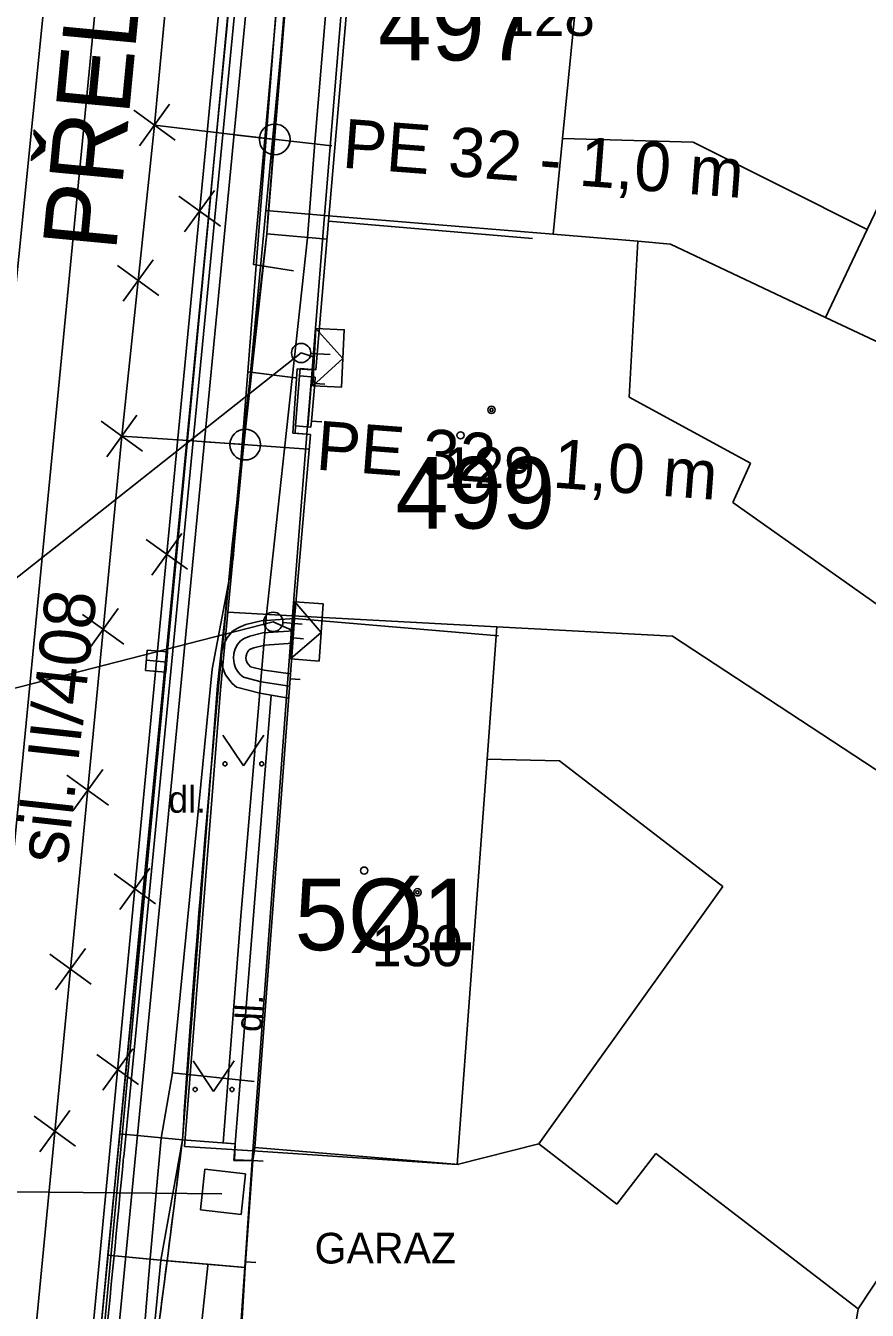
# Model space of a CAD drawing. Extents: x -643342 to -638635, y -1201752 to -1189948.
# Drawn here: x -639498.67 to -639478.12, y -1192813.04 to -1192781.64 of the extents above; entities that cross this region are included whole.
import ezdxf

# ---------------------------------------------------------------- set-up
doc = ezdxf.new("R2010")
doc.units = 0
for name, color, linetype in [('2', 7, 'Continuous'), ('IS_EL_NN_NADZEMNÍ', 7, 'Continuous'), ('IS_EL_NN_PODZEMNÍ', 7, 'Continuous'), ('IS_PLYN_STL', 7, 'Continuous'), ('IS_TELEF_MISTNI_ZAMERENO', 7, 'Continuous'), ('IS_VODOVOD_PRIPOJKA DOMOVNÍ', 7, 'Continuous'), ('IS_VODOVOD_PRIPOJKA HYDRANT', 7, 'Continuous'), ('K-HRANICE_KN', 7, 'Continuous'), ('K-SLUCKOVE CARY', 7, 'Continuous'), ('K-ČÍSLA_PARCEL', 7, 'Continuous'), ('kanalizace_dešťová_stávající', 7, 'Continuous'), ('N-CHODNIK', 7, 'Continuous'), ('N-KAN_DEST_TRASA-NÁVRH', 7, 'Continuous'), ('N-OBVOD STAVBY 06', 7, 'Continuous'), ('N-OSA', 7, 'Continuous'), ('N-rusene_vedeni', 7, 'Continuous'), ('N-SILNICE', 7, 'Continuous'), ('N-SRAFY_PLOCHY', 7, 'Continuous'), ('RWE_STL_PRIPOJKY', 7, 'Continuous'), ('RWE_STL_RADY', 7, 'Continuous'), ('tomaštík - Džuganovi - Vrstva 36', 7, 'Continuous'), ('Z-budovy', 7, 'Continuous'), ('Z-hrany_a_čáry', 7, 'Continuous'), ('Z-popisy', 7, 'Continuous'), ('Z-vchody_vjezdy', 7, 'Continuous'), ('Z-značky', 7, 'Continuous'), ('Z-šachty_poklopy', 7, 'Continuous')]:
    doc.layers.add(name, color=color, linetype=linetype)

msp = doc.modelspace()

# ---------------------------------------------------------------- linework, layer by layer
at = {"layer": '2'}
for centre in [(-639492.586, -1192784.42), (-639493.306, -1192791.88)]:
    msp.add_circle(centre, 0.375, dxfattribs=at)
at = {"layer": 'IS_EL_NN_NADZEMNÍ'}
for points in [[(-639491.653, -1192790.439), (-639490.92, -1192789.774), (-639491.585, -1192789.041)], [(-639491.705, -1192789.651), (-639491.235, -1192789.674)], [(-639492.202, -1192797.117), (-639491.453, -1192796.472), (-639492.098, -1192795.722)], [(-639492.386, -1192796.229), (-639491.917, -1192796.267)]]:
    msp.add_lwpolyline(points, dxfattribs=at)
for centre in [(-639491.94, -1192789.64), (-639492.62, -1192796.21)]:
    msp.add_circle(centre, 0.235, dxfattribs=at)
at = {"layer": 'IS_EL_NN_PODZEMNÍ'}
for p, q in [((-639503.93, -1192799.12), (-639491.94, -1192789.64)), ((-639491.94, -1192789.64), (-639491.62, -1192789.74)), ((-639503.93, -1192799.12), (-639492.62, -1192796.21)), ((-639492.62, -1192796.21), (-639492.15, -1192796.42))]:
    msp.add_line(p, q, dxfattribs=at)
for points in [[(-639491.653, -1192790.439), (-639491.585, -1192789.041), (-639490.886, -1192789.074), (-639490.954, -1192790.473)], [(-639492.202, -1192797.117), (-639492.098, -1192795.722), (-639491.401, -1192795.773), (-639491.504, -1192797.169)]]:
    msp.add_lwpolyline(points, close=True, dxfattribs=at)
at = {"layer": 'IS_PLYN_STL'}
for p, q in [((-639495.52, -1192784.07), (-639493.97, -1192767.19)), ((-639496.32, -1192791.67), (-639495.52, -1192784.07)), ((-639498.43, -1192813.58), (-639496.32, -1192791.67))]:
    msp.add_line(p, q, dxfattribs=at)
for points in [[(-639495.52, -1192784.07), (-639493.54, -1192784.31), (-639491.19, -1192784.58)], [(-639496.32, -1192791.67), (-639494.83, -1192791.77), (-639491.77, -1192791.99)]]:
    msp.add_lwpolyline(points, dxfattribs=at)
at = {"layer": 'IS_TELEF_MISTNI_ZAMERENO'}
for p, q in [((-639492.3, -1192778.08), (-639493.24, -1192790.1)), ((-639493.24, -1192790.1), (-639492.3, -1192778.08)), ((-639493.24, -1192790.1), (-639493.6, -1192794.66)), ((-639493.6, -1192794.66), (-639493.24, -1192790.1)), ((-639493.24, -1192790.1), (-639492.08, -1192790.25)), ((-639493.6, -1192794.66), (-639494.11, -1192797.37)), ((-639494.11, -1192797.37), (-639493.6, -1192794.66)), ((-639494.11, -1192797.37), (-639495.08, -1192807.23)), ((-639495.08, -1192807.23), (-639494.11, -1192797.37)), ((-639495.08, -1192807.23), (-639495.36, -1192808.83)), ((-639495.36, -1192808.83), (-639495.08, -1192807.23)), ((-639495.08, -1192807.23), (-639493.09, -1192807.44)), ((-639495.36, -1192808.83), (-639495.63, -1192811.77)), ((-639495.63, -1192811.77), (-639495.36, -1192808.83)), ((-639495.63, -1192811.77), (-639496.16, -1192818.41)), ((-639496.16, -1192818.41), (-639495.63, -1192811.77))]:
    msp.add_line(p, q, dxfattribs=at)
at = {"layer": 'IS_VODOVOD_PRIPOJKA DOMOVNÍ'}
msp.add_lwpolyline([(-639499.852, -1192774.557), (-639499.731, -1192774.571), (-639492.02, -1192775.45), (-639493.1, -1192787.48), (-639492.131, -1192787.636)], dxfattribs=at)
at = {"layer": 'IS_VODOVOD_PRIPOJKA HYDRANT'}
msp.add_lwpolyline([(-639503.418, -1192810.065), (-639503.2, -1192810.095), (-639493.88, -1192810.19)], dxfattribs=at)
at = {"layer": 'K-HRANICE_KN'}
for p, q in [((-639491.69, -1192774.35), (-639492.8, -1192786.16)), ((-639475.11, -1192780.31), (-639478.12, -1192786.62)), ((-639492.8, -1192786.16), (-639493.73, -1192795.97)), ((-639491.37, -1192786.28), (-639492.8, -1192786.16)), ((-639491.37, -1192786.28), (-639485.79, -1192786.74)), ((-639485.79, -1192786.74), (-639483.72, -1192786.91)), ((-639478.12, -1192786.62), (-639479.14, -1192788.77)), ((-639483.72, -1192786.91), (-639482.92, -1192786.98)), ((-639482.92, -1192786.98), (-639479.14, -1192788.77)), ((-639479.14, -1192788.77), (-639476.76, -1192789.89)), ((-639493.73, -1192795.97), (-639493.91, -1192797.87)), ((-639492.15, -1192796.06), (-639493.73, -1192795.97)), ((-639492.15, -1192796.06), (-639487.16, -1192796.33)), ((-639487.16, -1192796.33), (-639482.87, -1192796.56)), ((-639482.87, -1192796.56), (-639475.39, -1192801.48)), ((-639493.91, -1192797.87), (-639494.79, -1192809.03)), ((-639474.95, -1192807.86), (-639478.34, -1192813)), ((-639493.12, -1192809.14), (-639494.79, -1192809.03)), ((-639494.4, -1192827.84), (-639493.12, -1192809.14)), ((-639478.34, -1192813), (-639481.06, -1192829.36))]:
    msp.add_line(p, q, dxfattribs=at)
at = {"layer": 'K-SLUCKOVE CARY'}
for p, q in [((-639485.08, -1192779.59), (-639485.56, -1192784.4)), ((-639490.87, -1192780.14), (-639491.37, -1192786.28)), ((-639485.56, -1192784.4), (-639485.79, -1192786.74)), ((-639485.56, -1192784.4), (-639482.37, -1192784.49)), ((-639482.37, -1192784.49), (-639478.12, -1192786.62)), ((-639491.37, -1192786.28), (-639491.67, -1192790.05)), ((-639483.72, -1192786.91), (-639483.93, -1192790.72)), ((-639492.04, -1192790.03), (-639492.14, -1192791.6)), ((-639491.67, -1192790.05), (-639492.04, -1192790.03)), ((-639491.67, -1192790.05), (-639491.8, -1192791.62)), ((-639483.93, -1192790.72), (-639480.97, -1192792.33)), ((-639491.8, -1192791.62), (-639492.15, -1192796.06)), ((-639491.8, -1192791.62), (-639492.14, -1192791.6)), ((-639480.97, -1192792.33), (-639481.4, -1192793.29)), ((-639481.4, -1192793.29), (-639475.59, -1192797.41)), ((-639492.15, -1192796.06), (-639493.12, -1192809.14)), ((-639487.16, -1192796.33), (-639487.4, -1192799.57)), ((-639487.4, -1192799.57), (-639488.13, -1192809.47)), ((-639485.63, -1192799.61), (-639487.4, -1192799.57)), ((-639481.64, -1192802.68), (-639485.63, -1192799.61)), ((-639486.14, -1192808.97), (-639481.64, -1192802.68)), ((-639488.13, -1192809.47), (-639486.14, -1192808.97)), ((-639486.14, -1192808.97), (-639484.23, -1192810.44)), ((-639488.13, -1192809.47), (-639493.12, -1192809.14)), ((-639484.23, -1192810.44), (-639483.28, -1192809.2)), ((-639481.19, -1192810.81), (-639483.28, -1192809.2)), ((-639478.34, -1192813), (-639481.19, -1192810.81))]:
    msp.add_line(p, q, dxfattribs=at)
at = {"layer": 'K-ČÍSLA_PARCEL'}
for centre in [(-639488.048, -1192791.653), (-639490.402, -1192802.289)]:
    msp.add_circle(centre, 0.0875, dxfattribs=at)
at = {"layer": 'kanalizace_dešťová_stávající'}
msp.add_lwpolyline([(-639500.838, -1192858.606), (-639498.4, -1192827.95), (-639495.47, -1192797.17), (-639492.53, -1192766.39), (-639489.24, -1192732.18), (-639488.56, -1192730.68), (-639487.73, -1192718.33)], dxfattribs=at)
at = {"layer": 'N-CHODNIK'}
msp.add_lwpolyline([(-639495.215, -1192811.823), (-639493.308, -1192811.988), (-639493.3, -1192811.85), (-639493.12, -1192809.37), (-639493.569, -1192809.371), (-639493.551, -1192808.967), (-639494.84, -1192808.87)], close=True, dxfattribs=at)
at = {"layer": 'N-KAN_DEST_TRASA-NÁVRH'}
msp.add_lwpolyline([(-639498.884, -1192834.039), (-639503.116, -1192829.951), (-639498.124, -1192780.201), (-639493.988, -1192740.511), (-639490.998, -1192720.223)], dxfattribs=at)
at = {"layer": 'N-OBVOD STAVBY 06'}
for points in [[(-639490.763, -1192774.407), (-639491.607, -1192784.497), (-639491.784, -1192786.822), (-639492.345, -1192791.985), (-639492.793, -1192796.103), (-639493.413, -1192803.401), (-639493.844, -1192808.945)], [(-639494.218, -1192811.91), (-639493.308, -1192811.988), (-639493.12, -1192809.37), (-639493.581, -1192809.371), (-639493.551, -1192808.967), (-639493.844, -1192808.945)], [(-639494.218, -1192811.91), (-639494.222, -1192811.939), (-639494.961, -1192818.864)]]:
    msp.add_lwpolyline(points, dxfattribs=at)
at = {"layer": 'N-OSA'}
msp.add_lwpolyline([(-639495.549, -1192766.512), (-639499.658, -1192808.961)], dxfattribs=at)
at = {"layer": 'N-rusene_vedeni'}
for p, q in [((-639495.154, -1192783.563), (-639495.886, -1192784.577)), ((-639496.027, -1192783.704), (-639495.013, -1192784.436)), ((-639494.926, -1192785.808), (-639493.913, -1192786.539)), ((-639494.054, -1192785.667), (-639494.785, -1192786.68)), ((-639495.554, -1192787.363), (-639496.286, -1192788.377)), ((-639496.427, -1192787.504), (-639495.413, -1192788.236)), ((-639496.827, -1192791.304), (-639495.813, -1192792.036)), ((-639495.954, -1192791.163), (-639496.686, -1192792.177)), ((-639495.727, -1192794.194), (-639494.714, -1192794.926)), ((-639494.855, -1192794.054), (-639495.587, -1192795.067)), ((-639497.282, -1192796.027), (-639496.268, -1192796.758)), ((-639496.409, -1192795.886), (-639497.141, -1192796.899)), ((-639496.787, -1192799.815), (-639497.519, -1192800.828)), ((-639497.66, -1192799.955), (-639496.646, -1192800.687)), ((-639496.506, -1192802.367), (-639495.493, -1192803.099)), ((-639495.634, -1192802.226), (-639496.365, -1192803.239)), ((-639498.081, -1192804.332), (-639497.068, -1192805.064)), ((-639497.209, -1192804.191), (-639497.94, -1192805.205)), ((-639496.927, -1192806.783), (-639495.913, -1192807.515)), ((-639496.054, -1192806.642), (-639496.786, -1192807.656)), ((-639498.462, -1192808.29), (-639497.449, -1192809.021)), ((-639497.59, -1192808.149), (-639498.322, -1192809.162))]:
    msp.add_line(p, q, dxfattribs=at)
at = {"layer": 'N-SILNICE'}
for p, q in [((-639492.314, -1192766.825), (-639496.423, -1192809.274)), ((-639492.165, -1192766.839), (-639496.274, -1192809.288)), ((-639494.84, -1192808.87), (-639496.37, -1192808.722)), ((-639495.37, -1192811.81), (-639496.657, -1192811.685))]:
    msp.add_line(p, q, dxfattribs=at)
for centre, radius, start, end in [((-638654.028, -1192849.484), 841.096, 173.995633, 175.721181), ((-639079.22, -1192836.375), 416.529, 173.15477, 176.21376), ((-641212.11, -1192592.417), 1730.858, 352.569253, 352.816044), ((-654430.042, -1191365.485), 15003.249, 354.4395848, 354.4777819), ((-654430.042, -1191365.485), 15003.399, 354.4395848, 354.4777819)]:
    msp.add_arc(centre, radius, start, end, dxfattribs=at)
at = {"layer": 'N-SRAFY_PLOCHY'}
for p, q in [((-639493.753, -1192781.684), (-639492.4, -1192767.706)), ((-639494.927, -1192793.814), (-639493.753, -1192781.684)), ((-639495.981, -1192804.707), (-639494.927, -1192793.814)), ((-639496.939, -1192814.599), (-639495.981, -1192804.707)), ((-639496.37, -1192808.722), (-639496.657, -1192811.685)), ((-639494.84, -1192808.87), (-639496.37, -1192808.722)), ((-639495.215, -1192811.823), (-639494.84, -1192808.87)), ((-639496.657, -1192811.685), (-639497.331, -1192818.633)), ((-639495.215, -1192811.823), (-639496.657, -1192811.685)), ((-639496.657, -1192811.685), (-639495.215, -1192811.823)), ((-639495.77, -1192816.072), (-639495.215, -1192811.823))]:
    msp.add_line(p, q, dxfattribs=at)
for points in [[(-639493.747, -1192781.625), (-639494.005, -1192784.291), (-639494.312, -1192787.48), (-639494.548, -1192789.97), (-639494.823, -1192792.867), (-639495.07, -1192795.478), (-639495.359, -1192798.278), (-639495.518, -1192799.926), (-639495.721, -1192802.017), (-639495.878, -1192803.643), (-639496.151, -1192806.461), (-639496.37, -1192808.722), (-639494.84, -1192808.87), (-639494.591, -1192805.337), (-639494.289, -1192801.533), (-639493.965, -1192797.861), (-639493.757, -1192795.722), (-639493.595, -1192794.067), (-639493.293, -1192791.209), (-639492.885, -1192787.614), (-639492.78, -1192786.73), (-639492.363, -1192781.385)], [(-639495.215, -1192811.823), (-639493.308, -1192811.988), (-639493.3, -1192811.85), (-639493.12, -1192809.37), (-639493.569, -1192809.371), (-639493.551, -1192808.967), (-639494.84, -1192808.87), (-639495.215, -1192811.823)]]:
    msp.add_lwpolyline(points, dxfattribs=at)
at = {"layer": 'RWE_STL_PRIPOJKY'}
for p, q in [((-639493.58, -1192784.305), (-639492.586, -1192784.42)), ((-639494.304, -1192791.808), (-639493.306, -1192791.88))]:
    msp.add_line(p, q, dxfattribs=at)
at = {"layer": 'RWE_STL_RADY'}
msp.add_lwpolyline([(-639497.844, -1192828.492), (-639491.5, -1192762.757), (-639493.022, -1192762.61), (-639492.143, -1192753.805), (-639490.591, -1192738.259)], dxfattribs=at)
at = {"layer": 'Z-budovy'}
for p, q in [((-639490.733, -1192780.127), (-639491.27, -1192786.42)), ((-639491.27, -1192786.42), (-639491.58, -1192790.05)), ((-639491.27, -1192786.42), (-639486.288, -1192786.845)), ((-639486.288, -1192786.845), (-639491.27, -1192786.42)), ((-639491.964, -1192790.017), (-639491.98, -1192790.2)), ((-639491.98, -1192790.2), (-639491.596, -1192790.233)), ((-639491.58, -1192790.05), (-639491.964, -1192790.017)), ((-639491.609, -1192790.382), (-639491.687, -1192791.303)), ((-639491.596, -1192790.233), (-639491.609, -1192790.382)), ((-639492.08, -1192791.42), (-639492.09, -1192791.6)), ((-639491.7, -1192791.452), (-639492.08, -1192791.42)), ((-639491.687, -1192791.303), (-639491.7, -1192791.452)), ((-639491.716, -1192791.632), (-639492.1, -1192796.13)), ((-639492.09, -1192791.6), (-639491.716, -1192791.632)), ((-639492.1, -1192796.13), (-639492.136, -1192796.604)), ((-639487.118, -1192796.556), (-639492.1, -1192796.13)), ((-639492.1, -1192796.13), (-639487.118, -1192796.556)), ((-639492.136, -1192796.604), (-639492.211, -1192797.604)), ((-639492.211, -1192797.604), (-639493.07, -1192809.06)), ((-639493.07, -1192809.06), (-639493.12, -1192809.37)), ((-639493.07, -1192809.06), (-639488.087, -1192809.469)), ((-639488.087, -1192809.469), (-639493.07, -1192809.06)), ((-639493.12, -1192809.37), (-639493.3, -1192811.85)), ((-639493.3, -1192811.85), (-639493.39, -1192813.37))]:
    msp.add_line(p, q, dxfattribs=at)
at = {"layer": 'Z-hrany_a_čáry'}
for p, q in [((-639491.75, -1192774.21), (-639492.78, -1192786.73)), ((-639493.35, -1192777.33), (-639495.68, -1192801.91)), ((-639492.78, -1192786.73), (-639493.98, -1192797.77)), ((-639492.78, -1192786.73), (-639491.307, -1192786.856)), ((-639491.98, -1192790.2), (-639492.08, -1192791.42)), ((-639491.681, -1192790.226), (-639491.781, -1192791.445)), ((-639492.92, -1192796.182), (-639493.29, -1192796.277)), ((-639492.1, -1192796.13), (-639492.92, -1192796.182)), ((-639493.62, -1192796.44), (-639493.747, -1192796.601)), ((-639493.465, -1192796.351), (-639493.62, -1192796.44)), ((-639493.29, -1192796.277), (-639493.465, -1192796.351)), ((-639492.873, -1192796.48), (-639493.194, -1192796.562)), ((-639492.123, -1192796.432), (-639492.873, -1192796.48)), ((-639493.831, -1192796.757), (-639493.878, -1192796.929)), ((-639493.747, -1192796.601), (-639493.831, -1192796.757)), ((-639493.495, -1192796.766), (-639493.551, -1192796.869)), ((-639493.42, -1192796.671), (-639493.495, -1192796.766)), ((-639493.331, -1192796.62), (-639493.42, -1192796.671)), ((-639493.194, -1192796.562), (-639493.331, -1192796.62)), ((-639492.826, -1192796.777), (-639493.097, -1192796.847)), ((-639492.146, -1192796.734), (-639492.826, -1192796.777)), ((-639493.878, -1192796.929), (-639493.899, -1192797.108)), ((-639493.899, -1192797.108), (-639493.865, -1192797.315)), ((-639493.583, -1192796.986), (-639493.596, -1192797.101)), ((-639493.596, -1192797.101), (-639493.575, -1192797.232)), ((-639493.551, -1192796.869), (-639493.583, -1192796.986)), ((-639493.287, -1192797.044), (-639493.293, -1192797.094)), ((-639493.293, -1192797.094), (-639493.284, -1192797.15)), ((-639493.27, -1192796.981), (-639493.287, -1192797.044)), ((-639493.244, -1192796.932), (-639493.27, -1192796.981)), ((-639493.221, -1192796.903), (-639493.244, -1192796.932)), ((-639493.198, -1192796.889), (-639493.221, -1192796.903)), ((-639493.097, -1192796.847), (-639493.198, -1192796.889)), ((-639493.865, -1192797.315), (-639493.787, -1192797.504)), ((-639493.575, -1192797.232), (-639493.54, -1192797.338)), ((-639493.54, -1192797.338), (-639493.494, -1192797.418)), ((-639493.494, -1192797.418), (-639493.427, -1192797.497)), ((-639493.284, -1192797.15), (-639493.26, -1192797.208)), ((-639493.26, -1192797.208), (-639493.181, -1192797.313)), ((-639493.181, -1192797.313), (-639492.84, -1192797.395)), ((-639492.84, -1192797.395), (-639492.202, -1192797.479)), ((-639493.787, -1192797.504), (-639493.683, -1192797.646)), ((-639493.683, -1192797.646), (-639493.625, -1192797.717)), ((-639493.625, -1192797.717), (-639493.52, -1192797.81)), ((-639493.427, -1192797.497), (-639493.35, -1192797.561)), ((-639493.35, -1192797.561), (-639492.915, -1192797.676)), ((-639492.915, -1192797.676), (-639492.224, -1192797.779)), ((-639493.98, -1192797.77), (-639494.84, -1192808.87)), ((-639493.551, -1192808.967), (-639492.671, -1192798.003)), ((-639493.52, -1192797.81), (-639492.951, -1192797.954)), ((-639492.951, -1192797.954), (-639492.247, -1192798.078)), ((-639495.68, -1192801.91), (-639498.06, -1192827.63)), ((-639494.84, -1192808.87), (-639495.37, -1192811.81)), ((-639494.84, -1192808.87), (-639493.551, -1192808.967)), ((-639493.551, -1192808.967), (-639493.58, -1192809.36)), ((-639493.58, -1192809.36), (-639493.12, -1192809.37)), ((-639496, -1192818.52), (-639495.37, -1192811.81)), ((-639493.29, -1192811.99), (-639495.37, -1192811.81))]:
    msp.add_line(p, q, dxfattribs=at)
at = {"layer": 'Z-vchody_vjezdy'}
for p, q in [((-639491.609, -1192790.382), (-639491.687, -1192791.303)), ((-639491.36, -1192790.403), (-639491.609, -1192790.382)), ((-639491.438, -1192791.324), (-639491.687, -1192791.303)), ((-639492.136, -1192796.604), (-639492.211, -1192797.604)), ((-639491.887, -1192796.623), (-639492.136, -1192796.604)), ((-639491.962, -1192797.623), (-639492.211, -1192797.604)), ((-639493.12, -1192809.37), (-639493.3, -1192811.85)), ((-639492.871, -1192809.388), (-639493.12, -1192809.37)), ((-639493.051, -1192811.868), (-639493.3, -1192811.85))]:
    msp.add_line(p, q, dxfattribs=at)
at = {"layer": 'Z-značky'}
for p, q in [((-639493.851, -1192798.981), (-639493.351, -1192799.731)), ((-639493.351, -1192799.731), (-639492.851, -1192798.981)), ((-639494.579, -1192806.938), (-639494.079, -1192807.688)), ((-639494.079, -1192807.688), (-639493.579, -1192806.938))]:
    msp.add_line(p, q, dxfattribs=at)
for centre, radius in [((-639487.292, -1192791.03), 0.09), ((-639487.292, -1192791.03), 0.0398), ((-639493.801, -1192799.681), 0.05), ((-639492.902, -1192799.681), 0.05), ((-639489.101, -1192802.82), 0.09), ((-639489.101, -1192802.82), 0.0398), ((-639494.529, -1192807.638), 0.05), ((-639493.63, -1192807.638), 0.05)]:
    msp.add_circle(centre, radius, dxfattribs=at)
at = {"layer": 'Z-šachty_poklopy'}
for p, q in [((-639495.697, -1192796.9), (-639495.741, -1192797.398)), ((-639495.2, -1192796.943), (-639495.697, -1192796.9)), ((-639495.243, -1192797.441), (-639495.2, -1192796.943)), ((-639495.741, -1192797.398), (-639495.243, -1192797.441)), ((-639495.719, -1192797.149), (-639495.221, -1192797.192)), ((-639494.293, -1192809.589), (-639494.401, -1192810.583)), ((-639493.299, -1192809.697), (-639494.293, -1192809.589)), ((-639493.407, -1192810.691), (-639493.299, -1192809.697)), ((-639494.401, -1192810.583), (-639493.407, -1192810.691))]:
    msp.add_line(p, q, dxfattribs=at)

# ---------------------------------------------------------------- texts
at = {"layer": '2'}
msp.add_text('PŘELOŽKA 8 STL', height=1.8, rotation=84.5748, dxfattribs=at).set_placement((-639496.463, -1192787.181))
at = {"layer": 'K-ČÍSLA_PARCEL'}
for s, p in [('497', (-639490.06, -1192782.49)), ('499', (-639489.641, -1192793.93)), ('5%%c1', (-639492.098, -1192804.235))]:
    msp.add_text(s, height=1.75, dxfattribs=at).set_placement(p)
at = {"layer": 'RWE_STL_RADY'}
for p in [(-639490.959, -1192785.11), (-639491.6, -1192792.488)]:
    msp.add_text('PE 32 - 1,0 m', height=1.2, rotation=355.6623, dxfattribs=at).set_placement(p)
at = {"layer": 'tomaštík - Džuganovi - Vrstva 36'}
msp.add_text('sil. II/408', height=1.25, rotation=83.7004, dxfattribs=at).set_placement((-639497.661, -1192802.16))
at = {"layer": 'Z-popisy'}
for s, height, p in [('128', 1, (-639487.001, -1192781.891)), ('129', 1, (-639488.47, -1192792.942)), ('dl.', 0.65, (-639495.184, -1192800.875)), ('130', 1, (-639490.226, -1192804.626)), ('GARAZ', 0.75, (-639491.612, -1192811.891))]:
    msp.add_text(s, height=height, dxfattribs=at).set_placement(p)
msp.add_text('dl.', height=0.65, rotation=86.8737, dxfattribs=at).set_placement((-639492.912, -1192806.246))

doc.saveas('drawing.dxf')
